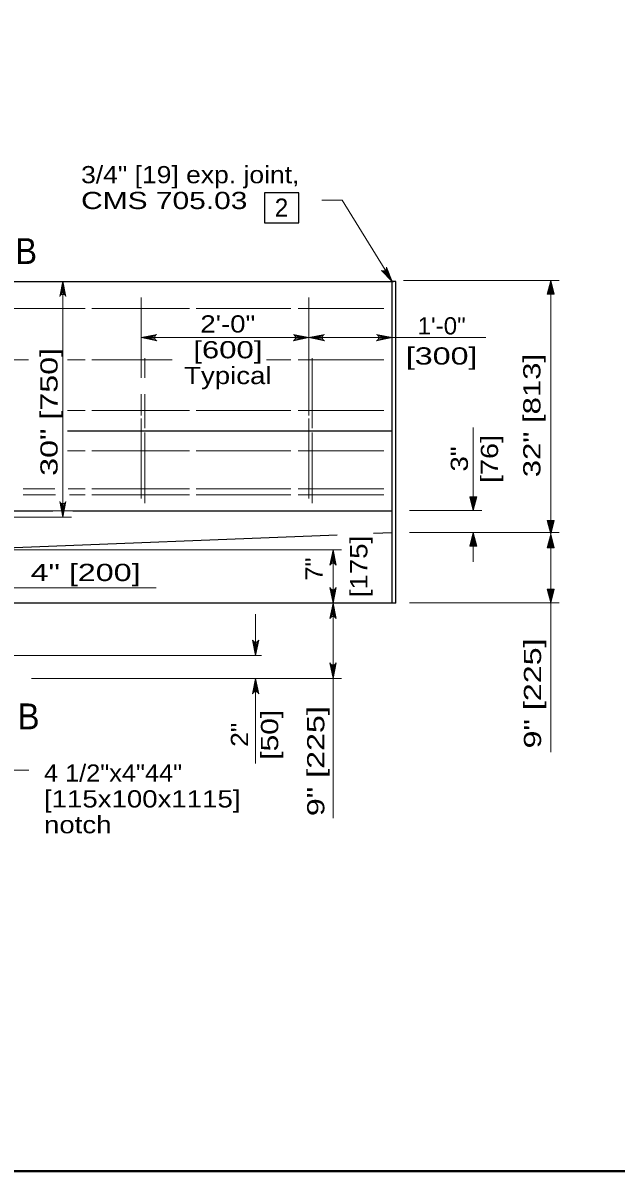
# Model space of a CAD drawing. Extents: x -1431.2 to -1397.2, y -1045.1 to -1001.1.
# Drawn here: x -1414.42 to -1408.95, y -1022.58 to -1011.99 of the extents above; entities that cross this region are included whole.
import ezdxf
from ezdxf.enums import TextEntityAlignment as Align

# ---------------------------------------------------------------- set-up
doc = ezdxf.new("R2010")
doc.units = 0
doc.header["$LTSCALE"] = 0.064
doc.layers.add('1', color=7, linetype='Continuous', lineweight=13)

msp = doc.modelspace()

# ---------------------------------------------------------------- hatches: boundary and pattern name
at = {"layer": '1'}
for points in [[(-1409.58533, -1014.48967), (-1409.55383, -1014.36358), (-1409.52225, -1014.48967)], [(-1410.23675, -1016.35783), (-1410.26825, -1016.48392), (-1410.29983, -1016.35783)], [(-1409.52225, -1016.57892), (-1409.55383, -1016.705), (-1409.58533, -1016.57892)], [(-1410.29983, -1016.81392), (-1410.26825, -1016.68783), (-1410.23675, -1016.81392)], [(-1409.58533, -1016.83108), (-1409.55383, -1016.705), (-1409.52225, -1016.83108)], [(-1409.52225, -1017.20983), (-1409.55383, -1017.33592), (-1409.58533, -1017.20983)]]:
    msp.add_hatch(color=256, dxfattribs=at).paths.add_polyline_path(points)

# ---------------------------------------------------------------- linework, layer by layer
for p, q in [((-1411.66708, -1013.62342), (-1411.47908, -1013.62342)), ((-1411.01817, -1014.37042), (-1411.47908, -1013.62342)), ((-1411.10208, -1014.27492), (-1411.01725, -1014.3715)), ((-1411.09258, -1014.27458), (-1411.01725, -1014.3715)), ((-1411.08192, -1014.27033), (-1411.01725, -1014.3715)), ((-1411.07517, -1014.2645), (-1411.01725, -1014.3715)), ((-1411.07008, -1014.25625), (-1411.01725, -1014.3715)), ((-1414.07642, -1014.499), (-1414.05642, -1014.36808)), ((-1414.068, -1014.49408), (-1414.05642, -1014.36808)), ((-1414.05642, -1016.54583), (-1414.05642, -1014.36808)), ((-1414.05642, -1014.49175), (-1414.05642, -1014.36808)), ((-1414.04725, -1014.49308), (-1414.05642, -1014.36808)), ((-1414.03825, -1014.4975), (-1414.05642, -1014.36808)), ((-1411.02983, -1014.3715), (-1411.00083, -1014.3715)), ((-1411.00083, -1014.3715), (-1411.02983, -1014.3715)), ((-1410.91225, -1014.36358), (-1409.47442, -1014.36358)), ((-1409.55383, -1018.71375), (-1409.55383, -1014.36358)), ((-1413.33208, -1014.51992), (-1413.33208, -1015.26125)), ((-1411.7855, -1014.51992), (-1411.7855, -1015.60892)), ((-1414.70258, -1014.62258), (-1413.85083, -1014.62258)), ((-1413.79017, -1014.62258), (-1412.88883, -1014.62258)), ((-1412.82658, -1014.62258), (-1411.95175, -1014.62258)), ((-1411.883, -1014.62258), (-1411.09442, -1014.62258)), ((-1413.20275, -1014.87192), (-1413.33208, -1014.89)), ((-1413.20708, -1014.88083), (-1413.33208, -1014.89)), ((-1411.91492, -1014.87192), (-1411.7855, -1014.89)), ((-1411.9105, -1014.88083), (-1411.7855, -1014.89)), ((-1411.65617, -1014.87192), (-1411.7855, -1014.89)), ((-1411.66058, -1014.88083), (-1411.7855, -1014.89)), ((-1411.14667, -1014.87192), (-1411.01725, -1014.89)), ((-1411.14225, -1014.88083), (-1411.01725, -1014.89)), ((-1413.20842, -1014.89), (-1413.33208, -1014.89)), ((-1413.20617, -1014.90167), (-1413.33208, -1014.89)), ((-1413.20125, -1014.91), (-1413.33208, -1014.89)), ((-1411.91642, -1014.91), (-1411.7855, -1014.89)), ((-1411.91142, -1014.90167), (-1411.7855, -1014.89)), ((-1411.90917, -1014.89), (-1411.7855, -1014.89)), ((-1411.66192, -1014.89), (-1411.7855, -1014.89)), ((-1411.65958, -1014.90167), (-1411.7855, -1014.89)), ((-1411.65467, -1014.91), (-1411.7855, -1014.89)), ((-1411.14817, -1014.91), (-1411.01725, -1014.89)), ((-1411.14325, -1014.90167), (-1411.01725, -1014.89)), ((-1411.14092, -1014.89), (-1411.01725, -1014.89)), ((-1414.70258, -1015.094), (-1414.37258, -1015.094)), ((-1414.01458, -1015.094), (-1413.85083, -1015.094)), ((-1413.79017, -1015.094), (-1413.0465, -1015.094)), ((-1413.30042, -1015.07958), (-1413.30042, -1015.26125)), ((-1412.17667, -1015.094), (-1411.95175, -1015.094)), ((-1411.883, -1015.094), (-1411.09442, -1015.094)), ((-1411.75383, -1015.07958), (-1411.75383, -1015.72717)), ((-1413.33208, -1015.41283), (-1413.33208, -1015.60892)), ((-1413.30042, -1015.41283), (-1413.30042, -1015.72717)), ((-1414.01458, -1015.56392), (-1413.85083, -1015.56392)), ((-1413.79017, -1015.56392), (-1412.88883, -1015.56392)), ((-1412.82658, -1015.56392), (-1411.95175, -1015.56392)), ((-1411.883, -1015.56392), (-1411.09442, -1015.56392)), ((-1413.33208, -1015.63667), (-1413.33208, -1016.37583)), ((-1411.7855, -1015.63667), (-1411.7855, -1016.37583)), ((-1410.26825, -1016.48392), (-1410.26825, -1015.71817)), ((-1413.30042, -1015.76483), (-1413.30042, -1016.41842)), ((-1411.75383, -1015.76483), (-1411.75383, -1016.41842)), ((-1414.01458, -1015.93567), (-1413.85083, -1015.93567)), ((-1413.79017, -1015.93567), (-1412.88883, -1015.93567)), ((-1412.82658, -1015.93567), (-1411.95175, -1015.93567)), ((-1411.883, -1015.93567), (-1411.09442, -1015.93567)), ((-1414.42342, -1016.28475), (-1414.12925, -1016.28475)), ((-1414.42342, -1016.34033), (-1414.12283, -1016.34033)), ((-1414.00742, -1016.28475), (-1413.85083, -1016.28475)), ((-1413.99458, -1016.34033), (-1413.85083, -1016.34033)), ((-1413.79017, -1016.28475), (-1412.88883, -1016.28475)), ((-1413.79017, -1016.34033), (-1412.88883, -1016.34033)), ((-1412.82658, -1016.28475), (-1411.95175, -1016.28475)), ((-1412.82658, -1016.34033), (-1411.95175, -1016.34033)), ((-1411.883, -1016.28475), (-1411.09442, -1016.28475)), ((-1411.883, -1016.34033), (-1411.09442, -1016.34033)), ((-1414.0745, -1016.4165), (-1414.05642, -1016.54583)), ((-1414.0655, -1016.42092), (-1414.05642, -1016.54583)), ((-1414.03642, -1016.415), (-1414.05642, -1016.54583)), ((-1414.04475, -1016.41992), (-1414.05642, -1016.54583)), ((-1414.05642, -1016.42225), (-1414.05642, -1016.54583)), ((-1414.922, -1016.54658), (-1413.9755, -1016.54658)), ((-1411.08033, -1016.48792), (-1414.53833, -1016.48792)), ((-1410.85642, -1016.48392), (-1410.18892, -1016.48392)), ((-1410.85642, -1016.68783), (-1409.47442, -1016.68783)), ((-1410.26825, -1016.95992), (-1410.26825, -1016.68783)), ((-1414.922, -1016.84758), (-1411.48458, -1016.84758)), ((-1411.58242, -1016.97842), (-1411.56242, -1016.84758)), ((-1411.574, -1016.9735), (-1411.56242, -1016.84758)), ((-1411.56242, -1016.84758), (-1411.56242, -1017.33992)), ((-1411.56242, -1016.97125), (-1411.56242, -1016.84758)), ((-1411.55325, -1016.97258), (-1411.56242, -1016.84758)), ((-1411.54433, -1016.97692), (-1411.56242, -1016.84758)), ((-1411.56242, -1016.84758), (-1411.56242, -1018.03408)), ((-1414.98508, -1017.19883), (-1413.19358, -1017.19883)), ((-1411.5805, -1017.21058), (-1411.56242, -1017.33992)), ((-1411.57158, -1017.21492), (-1411.56242, -1017.33992)), ((-1411.54242, -1017.209), (-1411.56242, -1017.33992)), ((-1411.55083, -1017.214), (-1411.56242, -1017.33992)), ((-1411.56242, -1017.21625), (-1411.56242, -1017.33992)), ((-1414.922, -1017.33992), (-1412.21383, -1017.33992)), ((-1411.58242, -1017.47083), (-1411.56242, -1017.33992)), ((-1411.574, -1017.46583), (-1411.56242, -1017.33992)), ((-1411.56242, -1017.33992), (-1411.56242, -1019.3255)), ((-1411.56242, -1017.46358), (-1411.56242, -1017.33992)), ((-1411.55325, -1017.46492), (-1411.56242, -1017.33992)), ((-1411.54433, -1017.46925), (-1411.56242, -1017.33992)), ((-1410.85642, -1017.33592), (-1409.47442, -1017.33592)), ((-1412.27683, -1017.44075), (-1412.27683, -1017.824)), ((-1412.295, -1017.69467), (-1412.27683, -1017.824)), ((-1412.286, -1017.699), (-1412.27683, -1017.824)), ((-1412.25683, -1017.69317), (-1412.27683, -1017.824)), ((-1412.26525, -1017.69808), (-1412.27683, -1017.824)), ((-1412.27683, -1017.70033), (-1412.27683, -1017.824)), ((-1414.563, -1017.824), (-1412.22208, -1017.824)), ((-1412.89783, -1017.82408), (-1412.89783, -1017.824)), ((-1411.5805, -1017.90467), (-1411.56242, -1018.03408)), ((-1411.57158, -1017.90908), (-1411.56242, -1018.03408)), ((-1411.54242, -1017.90317), (-1411.56242, -1018.03408)), ((-1411.55083, -1017.90817), (-1411.56242, -1018.03408)), ((-1411.56242, -1017.91042), (-1411.56242, -1018.03408)), ((-1414.34592, -1018.03408), (-1411.48458, -1018.03408)), ((-1412.29683, -1018.16492), (-1412.27683, -1018.03408)), ((-1412.2885, -1018.16), (-1412.27683, -1018.03408)), ((-1412.27683, -1018.15775), (-1412.27683, -1018.03408)), ((-1412.26775, -1018.15908), (-1412.27683, -1018.03408)), ((-1412.25875, -1018.16342), (-1412.27683, -1018.03408)), ((-1412.27683, -1018.03408), (-1412.27683, -1018.82017))]:
    msp.add_line(p, q, dxfattribs=at)
at = {"layer": '1', "lineweight": 25}
for p, q in [((-1426.97542, -1014.3715), (-1411.01725, -1014.3715)), ((-1411.03308, -1014.3715), (-1411.004, -1014.3715)), ((-1410.98275, -1014.3715), (-1411.01725, -1014.3715)), ((-1411.01725, -1015.41392), (-1411.01725, -1014.3715)), ((-1410.98275, -1015.46983), (-1410.98275, -1014.3715)), ((-1411.01725, -1017.33992), (-1411.01725, -1015.41392)), ((-1410.98275, -1017.33992), (-1410.98275, -1015.46983)), ((-1414.01458, -1015.74883), (-1411.01725, -1015.74883)), ((-1426.94317, -1016.48792), (-1414.14858, -1016.48792)), ((-1413.96392, -1016.48792), (-1411.01725, -1016.48792)), ((-1411.525, -1016.71175), (-1414.98508, -1016.84758)), ((-1411.01725, -1016.69183), (-1411.18892, -1016.69858))]:
    msp.add_line(p, q, dxfattribs=at)
for points in [[(-1397.74575, -1022.57983), (-1429.24575, -1022.57983), (-1429.24575, -1001.57983)], [(-1410.98275, -1017.33992), (-1411.01725, -1017.33992), (-1414.98508, -1017.33992)]]:
    msp.add_lwpolyline(points, dxfattribs=at)
at = {"layer": '1', "lineweight": 40}
msp.add_lwpolyline([(-1429.24575, -1001.57983), (-1397.74575, -1001.57983), (-1397.74575, -1022.57983), (-1429.24575, -1022.57983)], close=True, dxfattribs=at)
at = {"layer": '1', "lineweight": 25}
msp.add_lwpolyline([(-1412.195, -1013.55408), (-1412.195, -1013.83208), (-1411.87783, -1013.83208), (-1411.87783, -1013.55408)], close=True, dxfattribs=at)
at = {"layer": '1'}
for points in [[(-1411.11533, -1014.26958), (-1411.01725, -1014.3715), (-1411.06858, -1014.23967)], [(-1414.085, -1014.511), (-1414.05642, -1014.36808), (-1414.02783, -1014.511)], [(-1413.18917, -1014.91858), (-1413.33208, -1014.89), (-1413.18917, -1014.86142)], [(-1411.92842, -1014.91858), (-1411.7855, -1014.89), (-1411.92842, -1014.86142)], [(-1411.64267, -1014.91858), (-1411.7855, -1014.89), (-1411.64267, -1014.86142)], [(-1411.16017, -1014.91858), (-1411.01725, -1014.89), (-1411.16017, -1014.86142)], [(-1410.15133, -1014.89), (-1411.7855, -1014.89), (-1413.33208, -1014.89)], [(-1414.02783, -1016.403), (-1414.05642, -1016.54583), (-1414.085, -1016.403)], [(-1411.591, -1016.99042), (-1411.56242, -1016.84758), (-1411.53383, -1016.99042)], [(-1417.50675, -1016.97758), (-1414.66083, -1018.88217), (-1414.36975, -1018.88217)], [(-1411.53383, -1017.197), (-1411.56242, -1017.33992), (-1411.591, -1017.197)], [(-1411.591, -1017.48283), (-1411.56242, -1017.33992), (-1411.53383, -1017.48283)], [(-1412.24825, -1017.68117), (-1412.27683, -1017.824), (-1412.30542, -1017.68117)], [(-1411.53383, -1017.89117), (-1411.56242, -1018.03408), (-1411.591, -1017.89117)], [(-1412.30542, -1018.17692), (-1412.27683, -1018.03408), (-1412.24825, -1018.17692)]]:
    msp.add_lwpolyline(points, dxfattribs=at)
for points in [[(-1409.58533, -1014.48967), (-1409.55383, -1014.36358), (-1409.52225, -1014.48967)], [(-1410.23675, -1016.35783), (-1410.26825, -1016.48392), (-1410.29983, -1016.35783)], [(-1409.52225, -1016.57892), (-1409.55383, -1016.705), (-1409.58533, -1016.57892)], [(-1410.29983, -1016.81392), (-1410.26825, -1016.68783), (-1410.23675, -1016.81392)], [(-1409.58533, -1016.83108), (-1409.55383, -1016.705), (-1409.52225, -1016.83108)], [(-1409.52225, -1017.20983), (-1409.55383, -1017.33592), (-1409.58533, -1017.20983)]]:
    msp.add_lwpolyline(points, close=True, dxfattribs=at)
for centre, start, end in [((-1414.05635, -1014.52255), 22.08782, 157.91395), ((-1413.17767, -1014.88998), 112.08782, 247.91395), ((-1411.93995, -1014.88998), 292.08605, 67.91218), ((-1411.63109, -1014.88998), 112.08782, 247.91395), ((-1411.17171, -1014.88998), 292.08605, 67.91218), ((-1414.05641, -1016.39144), 202.08782, 337.91395), ((-1411.56238, -1017.002), 22.08782, 157.91395), ((-1411.56245, -1017.1855), 202.08782, 337.91395), ((-1411.56238, -1017.49436), 22.08782, 157.91395), ((-1412.2769, -1017.66959), 202.08782, 337.91395), ((-1411.56245, -1017.87964), 202.08782, 337.91395), ((-1412.27683, -1018.1885), 22.08782, 157.91395)]:
    msp.add_arc(centre, 0.03084, start, end, dxfattribs=at)
msp.add_ellipse((-1411.09801, -1014.24515), major_axis=(0.02654, 0.01384), ratio=0.999895, start_param=3.61501156, end_param=5.9856247, dxfattribs=at)

# ---------------------------------------------------------------- texts
for s, height, width, p in [('3/4" [19] exp. joint,', 0.1588, 1.15, (-1413.88775, -1013.46617)), ('CMS 705.03', 0.1588, 1.3, (-1413.88775, -1013.70433)), ('B', 0.2382, 0.95, (-1414.49633, -1014.21092)), ('4" [200]', 0.1588, 1.4, (-1414.35392, -1017.13642)), ('B', 0.2382, 0.95, (-1414.47317, -1018.50417)), ('4 1/2"x4"44"', 0.1588, 1.1, (-1414.23042, -1018.98733)), ('[115x100x1115]', 0.1588, 1.2, (-1414.23042, -1019.22542)), ('notch', 0.1588, 1.2, (-1414.23042, -1019.46358))]:
    msp.add_text(s, height=height, dxfattribs=dict(at, width=width)).set_placement(p)
msp.add_text('2', height=0.1682, dxfattribs=at).set_placement((-1412.10083, -1013.77508))
for s, width, p in [('2\'-0"', 1.2, (-1412.53358, -1014.84325)), ('1\'-0"', 1.05, (-1410.56046, -1014.861)), ('[600]', 1.35, (-1412.53358, -1015.08133)), ('[300]', 1.4, (-1410.56046, -1015.13883)), ('Typical', 1.2, (-1412.53354, -1015.3195))]:
    msp.add_text(s, height=0.1588, dxfattribs=dict(at, width=width)).set_placement(p, align=Align.CENTER)
for s, width, p in [('30" [750]', 1.4, (-1414.10467, -1016.1655)), ('32" [813]', 1.35, (-1409.64875, -1016.17842)), ('[175]', 1.2, (-1411.24583, -1017.28558)), ('9" [225]', 1.4, (-1409.64258, -1018.68083)), ('9" [225]', 1.4, (-1411.64283, -1019.30558))]:
    msp.add_text(s, height=0.1588, rotation=90, dxfattribs=dict(at, width=width)).set_placement(p)
for s, width, p in [('[76]', 1.25, (-1410.03992, -1016.01008)), ('3"', 1.2, (-1410.31775, -1016.01008)), ('7"', 1.1, (-1411.65908, -1017.02562)), ('[50]', 1.3, (-1412.06908, -1018.55467)), ('2"', 1.15, (-1412.34692, -1018.55467))]:
    msp.add_text(s, height=0.1588, rotation=90, dxfattribs=dict(at, width=width)).set_placement(p, align=Align.CENTER)

doc.saveas('drawing.dxf')
